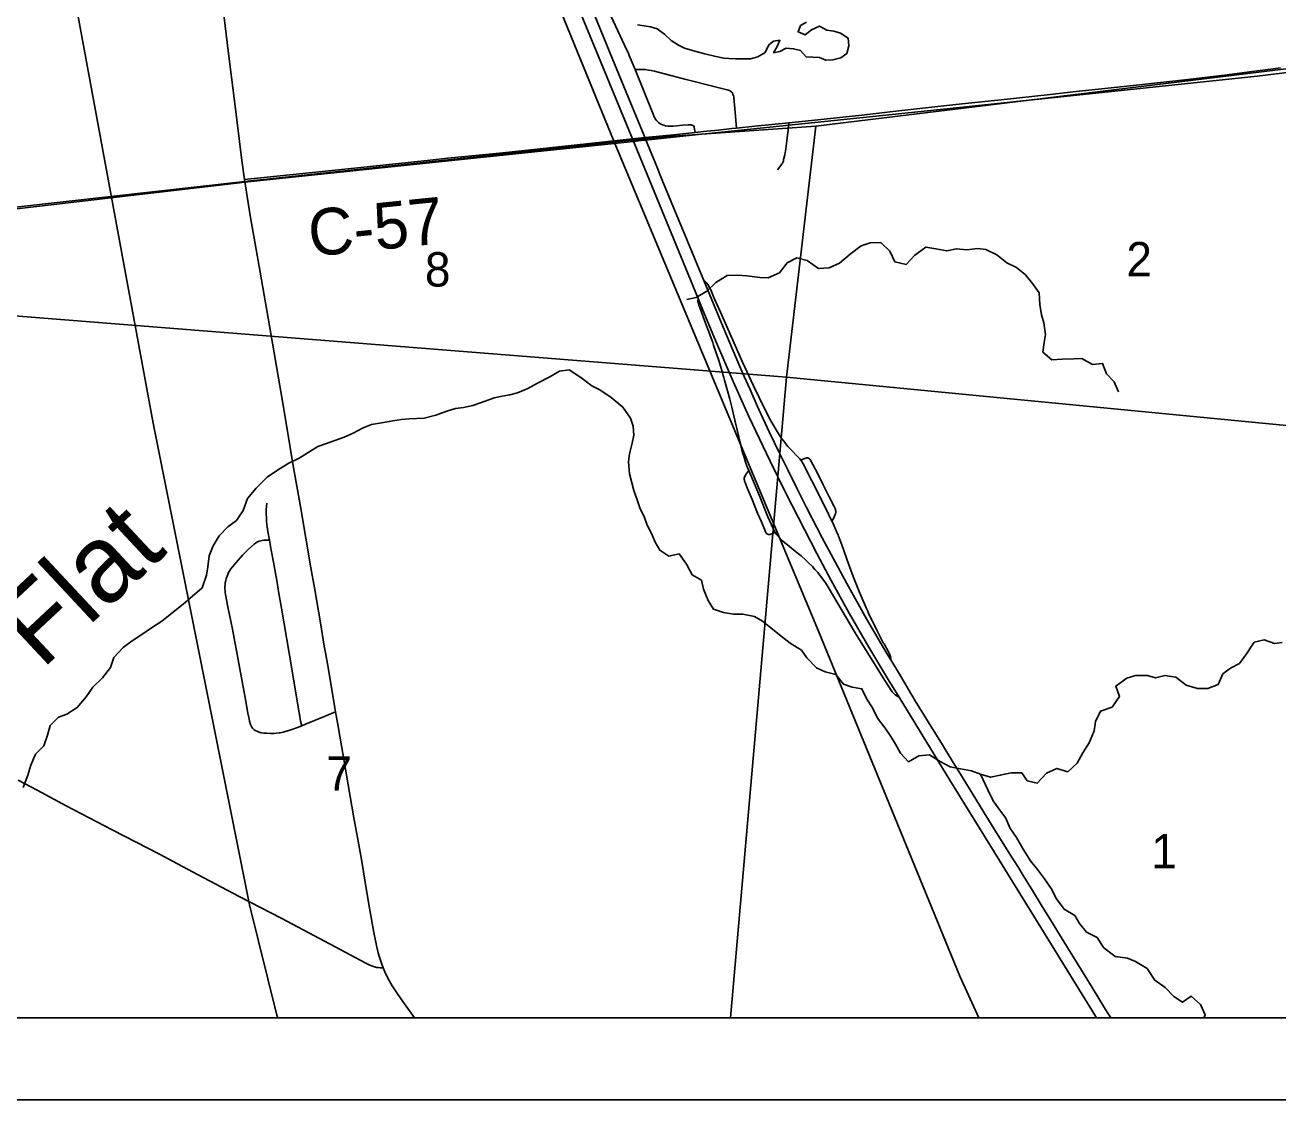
# Model space of a CAD drawing. Extents: x 0 to 34, y -5.4 to 22.
# Drawn here: x 6.179 to 7.705, y 14 to 15.309 of the extents above; entities that cross this region are included whole.
import ezdxf

# ---------------------------------------------------------------- set-up
doc = ezdxf.new("R2010")
doc.units = 0
for name, color, linetype in [('Default', 7, 'Continuous'), ('GM_X_County_Road', 7, 'Continuous'), ('GM_X_County_Road_Text', 7, 'Continuous'), ('GM_X_Interchange_Ramps', 7, 'Continuous'), ('GM_X_Minor_Lake', 7, 'Continuous'), ('GM_X_Minor_River', 7, 'Continuous'), ('GM_X_Minor_River_Text', 7, 'Continuous'), ('GM_X_Rail_Line', 7, 'Continuous'), ('GM_X_Section', 7, 'Continuous'), ('GM_X_Section_Text', 7, 'Continuous'), ('GM_X_Township_Road', 7, 'Continuous'), ('GM_X_US_Route', 7, 'Continuous'), ('SH_Data', 7, 'Continuous')]:
    doc.layers.add(name, color=color, linetype=linetype)

msp = doc.modelspace()

# ---------------------------------------------------------------- linework, layer by layer
at = {"layer": 'Default'}
for points in [[(6.0193, 14.1), (7.0382, 14.1), (7.1062, 14.8804), (6.1044, 14.9597)], [(7.0382, 14.1), (8.0569, 14.1), (8.0946, 14.5055), (8.0215, 14.7918), (7.1062, 14.8804)]]:
    msp.add_lwpolyline(points, close=True, dxfattribs=at)
at = {"layer": 'GM_X_County_Road'}
for points in [[(6.4464, 15.1211), (6.4431, 15.144), (6.4342, 15.2168), (6.4265, 15.2778), (6.4217, 15.3185), (6.4147, 15.3765), (6.4102, 15.4135), (6.4073, 15.4374), (6.4056, 15.4505), (6.4013, 15.4867), (6.3872, 15.6026), (6.3811, 15.6513), (6.3588, 15.8364), (6.3525, 15.8882), (6.3478, 15.927), (6.3428, 15.9686)], [(7.0093, 15.1798), (7.023, 15.1812), (7.0399, 15.183), (7.0453, 15.1835), (7.0677, 15.1859), (7.1092, 15.19), (7.1369, 15.1928), (7.1979, 15.1994), (7.2394, 15.2042), (7.3125, 15.2122), (7.3397, 15.2152), (7.3676, 15.2181), (7.4273, 15.2246), (7.4554, 15.2277), (7.5362, 15.2365), (7.5949, 15.2429), (7.643, 15.2487), (7.6702, 15.252), (7.6831, 15.2536), (7.6989, 15.2557), (7.7077, 15.2571)], [(6.4464, 15.1211), (6.5408, 15.1307), (6.5686, 15.1336), (6.6267, 15.1398), (6.6724, 15.1446), (6.694, 15.1468), (6.7607, 15.1537), (6.8292, 15.161), (6.9036, 15.169), (6.9188, 15.1706)], [(6.9188, 15.1706), (6.9338, 15.172), (6.9431, 15.1729), (6.9688, 15.1755), (6.9953, 15.1783), (7.0054, 15.1794), (7.0093, 15.1798)], [(6.6534, 14.1), (6.6411, 14.1172), (6.6335, 14.1279), (6.6262, 14.1388), (6.6212, 14.1475), (6.6172, 14.1559), (6.6152, 14.161), (6.6134, 14.1652), (6.6127, 14.1676), (6.6111, 14.1726), (6.6104, 14.1752), (6.6092, 14.1793), (6.6074, 14.1862), (6.6038, 14.2039), (6.5975, 14.2404), (6.5932, 14.2652), (6.5887, 14.2928), (6.5847, 14.3151), (6.5796, 14.3435), (6.5726, 14.3839), (6.5661, 14.4219), (6.5604, 14.455), (6.5585, 14.4662), (6.5573, 14.4727), (6.5565, 14.4774), (6.554, 14.4924), (6.5473, 14.531), (6.5453, 14.5426), (6.5435, 14.5526), (6.5387, 14.5812), (6.5314, 14.6236), (6.5272, 14.6481), (6.5149, 14.7202), (6.5053, 14.7747), (6.4983, 14.817), (6.4912, 14.858), (6.4784, 14.9334), (6.4652, 15.008), (6.4533, 15.0773), (6.4464, 15.1211)], [(6.1707, 14.3893), (6.194, 14.3771), (6.229, 14.3581), (6.2852, 14.329), (6.3426, 14.2993), (6.3646, 14.2877), (6.39, 14.2743), (6.4398, 14.2479), (6.4916, 14.2209), (6.5507, 14.1896), (6.5939, 14.1666), (6.5988, 14.1641), (6.6021, 14.1627), (6.6047, 14.162), (6.6071, 14.1614), (6.6095, 14.1611), (6.6116, 14.161), (6.6152, 14.161)]]:
    msp.add_lwpolyline(points, dxfattribs=at)
at = {"layer": 'GM_X_Interchange_Ramps'}
for points in [[(7.2333, 14.536), (7.2333, 14.538), (7.2329, 14.5403), (7.2323, 14.542), (7.2311, 14.5448), (7.2251, 14.5553), (7.2242, 14.5567), (7.2234, 14.5583), (7.2166, 14.5715), (7.2063, 14.5929), (7.2048, 14.5961), (7.2035, 14.5992), (7.1973, 14.6134), (7.1963, 14.6155), (7.1956, 14.6173), (7.189, 14.6335), (7.1882, 14.6356), (7.1874, 14.6376), (7.1818, 14.6531), (7.1739, 14.676), (7.1698, 14.6865), (7.1692, 14.6882), (7.1682, 14.6904), (7.1639, 14.7001), (7.1626, 14.703), (7.1617, 14.7049), (7.1533, 14.7219), (7.137, 14.754), (7.1267, 14.7746), (7.1254, 14.7767), (7.124, 14.7788), (7.1237, 14.7792), (7.1224, 14.7809), (7.1208, 14.7826), (7.1109, 14.7928), (7.1079, 14.796), (7.1056, 14.7989), (7.1029, 14.8024), (7.1007, 14.8053), (7.0974, 14.8102), (7.0948, 14.8141), (7.0885, 14.8249), (7.0876, 14.8264), (7.0868, 14.8281), (7.0798, 14.8413), (7.066, 14.8698), (7.0526, 14.8985), (7.0259, 14.9595), (7.018, 14.9773), (7.014, 14.9866), (7.0123, 14.99), (7.0108, 14.9928), (7.0094, 14.9947), (7.0076, 14.9965), (7.0056, 14.9979)], [(6.9986, 14.9762), (6.9985, 14.973), (6.999, 14.97), (6.9997, 14.9677), (7.0007, 14.965), (7.0066, 14.9493), (7.0153, 14.9257), (7.0165, 14.9224), (7.0176, 14.9191), (7.0242, 14.8994), (7.0259, 14.8937), (7.0279, 14.887), (7.029, 14.8834), (7.0301, 14.8798), (7.0309, 14.8767), (7.0317, 14.8738), (7.0372, 14.8533), (7.0385, 14.8486), (7.0397, 14.8439), (7.0439, 14.8263), (7.0506, 14.7975), (7.0512, 14.7947), (7.052, 14.7913), (7.0532, 14.7873), (7.0542, 14.784), (7.057, 14.7756), (7.0578, 14.7735), (7.0586, 14.7712), (7.0604, 14.7667), (7.0617, 14.7637), (7.0736, 14.7356), (7.0837, 14.7103), (7.09, 14.696), (7.0913, 14.6933), (7.0927, 14.6912), (7.093, 14.6906), (7.0945, 14.6884), (7.0964, 14.6862), (7.0986, 14.6838), (7.1012, 14.6814), (7.1044, 14.6786), (7.1074, 14.6761), (7.1195, 14.6664), (7.124, 14.6626), (7.1298, 14.6575), (7.1339, 14.6535), (7.1378, 14.6497), (7.141, 14.6462), (7.1445, 14.6423), (7.1491, 14.6364), (7.1541, 14.6293), (7.1625, 14.6155), (7.1898, 14.5689), (7.2259, 14.5108), (7.2352, 14.4971), (7.2366, 14.4953), (7.2387, 14.4932), (7.2411, 14.4917), (7.2435, 14.4906)], [(7.1617, 14.7049), (7.163, 14.7074), (7.1644, 14.7102), (7.1652, 14.7122), (7.1658, 14.714), (7.1663, 14.7157), (7.1664, 14.7171), (7.1662, 14.718), (7.166, 14.7189), (7.1656, 14.7203), (7.1641, 14.7235), (7.1584, 14.7347), (7.1511, 14.7493), (7.1445, 14.7624), (7.1383, 14.7739), (7.135, 14.78), (7.1343, 14.7809), (7.1333, 14.7816), (7.1324, 14.7819), (7.1317, 14.782), (7.1307, 14.7819), (7.1299, 14.7817), (7.1261, 14.7802), (7.1237, 14.7792)], [(7.0604, 14.7667), (7.0593, 14.7651), (7.0577, 14.7628), (7.0564, 14.7609), (7.0556, 14.7595), (7.0552, 14.7583), (7.0549, 14.7571), (7.0549, 14.7559), (7.055, 14.7549), (7.0553, 14.7538), (7.056, 14.7518), (7.0586, 14.7453), (7.0645, 14.7312), (7.0712, 14.7145), (7.0757, 14.7039), (7.081, 14.6911), (7.0815, 14.6902), (7.0824, 14.6895), (7.083, 14.689), (7.0843, 14.6887), (7.0855, 14.6887), (7.0863, 14.6888), (7.0871, 14.689), (7.0892, 14.6898), (7.0914, 14.6907), (7.0927, 14.6912)]]:
    msp.add_lwpolyline(points, dxfattribs=at)
at = {"layer": 'GM_X_Minor_Lake'}
msp.add_lwpolyline([(6.9247, 15.3094), (6.9331, 15.3081), (6.9406, 15.3068), (6.9489, 15.3044), (6.9583, 15.2975), (6.9658, 15.2905), (6.9748, 15.2847), (6.9823, 15.2808), (6.9974, 15.2767), (7.0068, 15.2739), (7.0204, 15.2707), (7.0302, 15.269), (7.0363, 15.2685), (7.0442, 15.268), (7.0533, 15.2679), (7.0624, 15.2681), (7.0716, 15.2703), (7.0804, 15.2758), (7.0847, 15.2849), (7.0904, 15.2897), (7.0984, 15.2907), (7.0949, 15.2832), (7.0906, 15.2753), (7.0982, 15.2771), (7.1058, 15.2811), (7.1149, 15.2802), (7.1232, 15.2782), (7.1303, 15.2705), (7.1386, 15.27), (7.1466, 15.2698), (7.1541, 15.2663), (7.1628, 15.2666), (7.1723, 15.2691), (7.18, 15.2746), (7.1824, 15.2837), (7.1814, 15.2932), (7.172, 15.2991), (7.1641, 15.3015), (7.1554, 15.3027), (7.1464, 15.3078), (7.1369, 15.3034), (7.1292, 15.2974), (7.1205, 15.301), (7.1233, 15.3085), (7.1305, 15.3128)], dxfattribs=at)
at = {"layer": 'GM_X_Minor_River'}
for points in [[(6.9848, 14.975), (6.9965, 14.9771), (7.0092, 14.9849), (7.0203, 14.9957), (7.0341, 15.0041), (7.0462, 15.0047), (7.0579, 15.0037), (7.0738, 15.0016), (7.084, 15.0014), (7.0977, 15.0072), (7.107, 15.0196), (7.1188, 15.0255), (7.1316, 15.0222), (7.1451, 15.0125), (7.1584, 15.0134), (7.171, 15.0193), (7.184, 15.03), (7.1974, 15.0401), (7.2081, 15.0437), (7.2213, 15.0442), (7.2321, 15.0338), (7.2383, 15.0208), (7.2519, 15.0175), (7.2627, 15.0287), (7.2761, 15.0387), (7.2882, 15.0366), (7.3014, 15.0341), (7.3132, 15.0366), (7.326, 15.0352), (7.3389, 15.0369), (7.3491, 15.0359), (7.3626, 15.0293), (7.3746, 15.0196), (7.3866, 15.0137), (7.3974, 15.0048), (7.4059, 14.9944), (7.4141, 14.9829), (7.415, 14.9688), (7.417, 14.9563), (7.4199, 14.9464), (7.4219, 14.9323), (7.4202, 14.9225), (7.4185, 14.9107), (7.4293, 14.9014), (7.4422, 14.902), (7.4566, 14.9025), (7.4661, 14.9031), (7.4788, 14.8957), (7.4913, 14.897), (7.496, 14.8844), (7.5053, 14.8747), (7.5108, 14.8625)], [(6.513, 14.7816), (6.5226, 14.7879), (6.5356, 14.796), (6.5451, 14.7989), (6.5565, 14.8033), (6.5676, 14.8073), (6.5786, 14.812), (6.5909, 14.8186), (6.6011, 14.8226), (6.6133, 14.8247), (6.627, 14.8271), (6.6376, 14.8288), (6.647, 14.8294), (6.6652, 14.8303), (6.6793, 14.8338), (6.6938, 14.8393), (6.7033, 14.8421), (6.7128, 14.8435), (6.7245, 14.8456), (6.7394, 14.851), (6.7504, 14.855), (6.7599, 14.8571), (6.7694, 14.8588), (6.7789, 14.8613), (6.7915, 14.8664), (6.8033, 14.8731), (6.8182, 14.8808), (6.8297, 14.8874), (6.8418, 14.8891), (6.8557, 14.8797), (6.8691, 14.8697), (6.8789, 14.8649), (6.8927, 14.8556), (6.9069, 14.8436), (6.9165, 14.8305), (6.9197, 14.8206), (6.9203, 14.8096), (6.9183, 14.7998), (6.915, 14.787), (6.9141, 14.7771), (6.915, 14.7627), (6.9175, 14.7532), (6.9203, 14.7421), (6.925, 14.7295), (6.9283, 14.72), (6.933, 14.7104), (6.9366, 14.7001), (6.9421, 14.6898), (6.9465, 14.6795), (6.952, 14.6695), (6.9629, 14.6621), (6.9758, 14.6649), (6.9847, 14.6527), (6.9913, 14.6396), (7.0029, 14.633), (7.0053, 14.622), (7.0108, 14.6082), (7.0174, 14.5979), (7.0295, 14.5935), (7.0419, 14.5918), (7.0533, 14.5916), (7.0672, 14.5887), (7.0773, 14.5832), (7.0874, 14.575), (7.0997, 14.565), (7.1109, 14.5561), (7.1244, 14.5479), (7.1311, 14.5383), (7.143, 14.5263), (7.1535, 14.5212), (7.1663, 14.5183), (7.1756, 14.5064), (7.1861, 14.5028), (7.1982, 14.5007), (7.204, 14.4881), (7.211, 14.4774), (7.2173, 14.4651), (7.2265, 14.4528), (7.2335, 14.4428), (7.2391, 14.4333), (7.2453, 14.4222), (7.255, 14.4118), (7.2676, 14.4191), (7.2805, 14.4204), (7.2936, 14.4122), (7.3056, 14.4056), (7.3184, 14.4031), (7.3316, 14.401), (7.3425, 14.3966), (7.3549, 14.393), (7.3667, 14.3954), (7.38, 14.3982), (7.3929, 14.3984), (7.3995, 14.3888), (7.4116, 14.3856), (7.4228, 14.3979), (7.4357, 14.4037), (7.4489, 14.3997), (7.4601, 14.4101), (7.4671, 14.4229), (7.4749, 14.4349)], [(6.1767, 14.3803), (6.1823, 14.3954), (6.1863, 14.4078), (6.1918, 14.421), (6.2018, 14.4311), (6.2065, 14.4443), (6.2098, 14.456), (6.2198, 14.4661), (6.23, 14.4697), (6.2427, 14.4778), (6.2535, 14.4909), (6.2616, 14.5029), (6.2732, 14.5141), (6.2832, 14.5265), (6.2872, 14.5389), (6.2984, 14.5512), (6.3095, 14.559), (6.3202, 14.566), (6.3344, 14.5757), (6.3455, 14.5831), (6.3577, 14.5927), (6.3716, 14.6039), (6.3831, 14.6135), (6.3946, 14.6236), (6.4002, 14.639), (6.4015, 14.6493), (6.4032, 14.6625), (6.4083, 14.6749), (6.4153, 14.6869), (6.4261, 14.6981), (6.4365, 14.7056), (6.4446, 14.7179), (6.4498, 14.7323), (6.4606, 14.745), (6.4741, 14.7584), (6.4878, 14.768), (6.5005, 14.7754), (6.513, 14.7816)], [(7.4749, 14.4349), (7.4808, 14.4496), (7.4825, 14.461), (7.4887, 14.4734), (7.5028, 14.4784), (7.5118, 14.4912), (7.5074, 14.5041), (7.5208, 14.5138), (7.5315, 14.517), (7.5459, 14.5171), (7.5557, 14.5139), (7.5671, 14.5168), (7.5803, 14.515), (7.593, 14.505), (7.6069, 14.5009), (7.6194, 14.5011), (7.632, 14.5058), (7.6375, 14.519), (7.6471, 14.5257), (7.6578, 14.5315), (7.6667, 14.5435), (7.676, 14.5574), (7.6881, 14.5602), (7.7005, 14.5558), (7.71, 14.5572)], [(7.3426, 14.3966), (7.3517, 14.3775), (7.3582, 14.3641), (7.366, 14.353), (7.3734, 14.343), (7.3781, 14.3315), (7.3863, 14.3196), (7.3947, 14.3054), (7.4036, 14.2913), (7.4121, 14.2805), (7.4206, 14.2694), (7.4287, 14.2575), (7.4353, 14.2448), (7.4446, 14.2322), (7.4573, 14.2247), (7.4632, 14.2148), (7.4717, 14.2044), (7.4845, 14.1977), (7.4922, 14.1855), (7.5064, 14.1746), (7.5215, 14.1728), (7.5313, 14.1685), (7.5455, 14.1599), (7.5548, 14.1457), (7.5675, 14.1371), (7.5779, 14.126), (7.5887, 14.1189), (7.5991, 14.1264), (7.6103, 14.1163), (7.6161, 14.1037), (7.6147, 14.1)]]:
    msp.add_lwpolyline(points, dxfattribs=at)
at = {"layer": 'GM_X_Rail_Line'}
for points in [[(4.0439, 14.8538), (4.7395, 14.9295), (4.8765, 14.9444), (6.1164, 15.0793), (6.4403, 15.1171), (6.4463, 15.1177), (6.92, 15.1674), (6.9294, 15.1684), (6.9348, 15.169), (6.9914, 15.1749), (7.0389, 15.1799), (7.3134, 15.2082), (7.6796, 15.247), (7.6929, 15.2483), (7.8942, 15.2734), (7.8983, 15.2739), (8.1702, 15.3079), (8.1991, 15.5295), (8.9, 15.5944), (8.9, 19.2127)], [(6.1298, 17.0307), (6.0905, 16.9105), (6.0657, 16.8233), (6.0521, 16.7659), (6.0427, 16.7106), (6.0374, 16.6619), (6.0337, 16.61), (6.035, 16.5368), (6.0346, 16.4766), (6.0418, 16.428), (6.0526, 16.3516), (6.0987, 16.1024), (6.1764, 15.688), (6.2405, 15.3368), (6.3349, 14.8243), (6.4523, 14.2374), (6.4858, 14.1034), (6.4871, 14.1)], [(6.1298, 17.0307), (6.1657, 16.9396), (6.2331, 16.7878), (6.3387, 16.522), (6.5579, 15.9912), (6.6517, 15.7661), (6.8965, 15.1669), (7.1452, 14.5708), (7.2659, 14.2765), (7.3176, 14.1508), (7.3404, 14.1)]]:
    msp.add_lwpolyline(points, dxfattribs=at)
msp.add_lwpolyline([(2.9527, 14.1), (8.0559, 14.1), (8.0925, 14.4946), (8.0933, 14.5029), (8.1066, 14.6429), (8.1702, 15.3079), (7.8983, 15.2739), (7.8942, 15.2734), (7.6929, 15.2483), (7.6796, 15.247), (7.3134, 15.2082), (7.0389, 15.1799), (6.9914, 15.1749), (6.9348, 15.169), (6.9294, 15.1684), (6.92, 15.1674), (6.4463, 15.1177), (6.4403, 15.1171), (6.1164, 15.0793), (4.8765, 14.9444), (4.7395, 14.9295), (4.0439, 14.8538), (3.0059, 14.7462), (2.9641, 14.2324)], close=True, dxfattribs=at)
at = {"layer": 'GM_X_Section'}
for points in [[(7.7181, 15.2564), (7.8967, 15.2761), (8.0215, 14.7918), (7.1062, 14.8804), (7.1421, 15.1859)], [(7.1421, 15.1859), (7.1062, 14.8804), (6.1044, 14.9597), (6.1164, 15.0815), (6.4432, 15.1181), (6.9566, 15.1729)]]:
    msp.add_lwpolyline(points, close=True, dxfattribs=at)
at = {"layer": 'GM_X_Township_Road'}
for points in [[(6.9953, 15.1783), (6.9945, 15.1824), (6.9938, 15.185), (6.9931, 15.1862), (6.9924, 15.1867), (6.9911, 15.1872), (6.9901, 15.1875), (6.9887, 15.1877), (6.9867, 15.1876), (6.98, 15.1873), (6.9682, 15.1861), (6.9658, 15.1859), (6.9636, 15.1858), (6.9614, 15.1861), (6.9589, 15.1865), (6.9569, 15.187), (6.9552, 15.1876), (6.9533, 15.1886), (6.952, 15.1894), (6.9504, 15.1905), (6.9491, 15.1917), (6.9481, 15.1929), (6.9468, 15.1947), (6.9453, 15.1974), (6.9439, 15.2006), (6.922, 15.2548), (6.9149, 15.2719), (6.9138, 15.2748), (6.912, 15.2785), (6.8979, 15.3082), (6.8892, 15.3271)], [(6.922, 15.2548), (6.928, 15.255), (6.9314, 15.2551), (6.9345, 15.2548), (6.9383, 15.2541), (6.9414, 15.2536), (6.9456, 15.2528), (6.9579, 15.2498), (6.9826, 15.2434), (7.0242, 15.2326), (7.0339, 15.2302), (7.0369, 15.2293), (7.0382, 15.2285), (7.0394, 15.2276), (7.04, 15.2269), (7.0405, 15.2261), (7.0411, 15.2247), (7.0417, 15.2233), (7.0421, 15.2219), (7.0424, 15.2204), (7.044, 15.2032), (7.045, 15.1879), (7.0453, 15.1835)], [(7.0952, 15.1329), (7.0995, 15.1382), (7.1007, 15.1399), (7.1013, 15.141), (7.1021, 15.1425), (7.1025, 15.1438), (7.1028, 15.1453), (7.1031, 15.1466), (7.1041, 15.1511), (7.1054, 15.1584), (7.1068, 15.1683), (7.1077, 15.175), (7.1083, 15.1807), (7.1088, 15.1853), (7.1092, 15.19)], [(6.5161, 14.4557), (6.5147, 14.4613), (6.5142, 14.4636), (6.5135, 14.4668), (6.5128, 14.4713), (6.5081, 14.5004), (6.5039, 14.5251), (6.4914, 14.5988), (6.4879, 14.6192), (6.486, 14.6303), (6.4816, 14.6551), (6.4789, 14.6695), (6.4766, 14.6818), (6.4748, 14.6921), (6.4741, 14.6978), (6.4733, 14.7045), (6.4729, 14.7099), (6.4728, 14.7129), (6.4728, 14.716), (6.4728, 14.7186), (6.4732, 14.7231), (6.4736, 14.7268)], [(6.5573, 14.4727), (6.5445, 14.4675), (6.5206, 14.4576), (6.5161, 14.4557), (6.5108, 14.4537), (6.5038, 14.451), (6.5003, 14.4499), (6.496, 14.4486), (6.4932, 14.4479), (6.4899, 14.4472), (6.4884, 14.447), (6.4848, 14.4466), (6.482, 14.4463), (6.4779, 14.4463), (6.4734, 14.4466), (6.4698, 14.4467), (6.4665, 14.4472), (6.4642, 14.448), (6.4614, 14.449), (6.4594, 14.4499), (6.4581, 14.4509), (6.4573, 14.4516), (6.4561, 14.4528), (6.4553, 14.4541), (6.4544, 14.4557), (6.4538, 14.4572), (6.4533, 14.4586), (6.4526, 14.4612), (6.4519, 14.4642), (6.4505, 14.471), (6.4475, 14.4878), (6.4316, 14.5734), (6.4296, 14.5831), (6.4282, 14.5906), (6.4262, 14.6004), (6.4233, 14.6157), (6.4229, 14.6179), (6.4227, 14.6201), (6.4225, 14.6225), (6.4224, 14.6249), (6.4227, 14.6278), (6.4229, 14.6299), (6.4236, 14.6327), (6.4241, 14.6351), (6.4251, 14.6379), (6.426, 14.64), (6.427, 14.6423), (6.4286, 14.6448), (6.4298, 14.6467), (6.4317, 14.6494), (6.4361, 14.6545), (6.4439, 14.6635), (6.451, 14.6706), (6.458, 14.6769), (6.4603, 14.6784), (6.462, 14.6796), (6.4632, 14.6801), (6.4642, 14.6806), (6.4663, 14.6811), (6.468, 14.6814), (6.4699, 14.6816), (6.4766, 14.6818)]]:
    msp.add_lwpolyline(points, dxfattribs=at)
at = {"layer": 'GM_X_US_Route'}
for points in [[(6.513, 16.1582), (6.5275, 16.1223), (6.5729, 16.0113), (6.5938, 15.9611), (6.6401, 15.8489), (6.6602, 15.7999), (6.6913, 15.724), (6.7164, 15.6624), (6.7363, 15.6145), (6.8369, 15.3693), (6.8669, 15.2965), (6.9119, 15.1873), (6.9188, 15.1706)], [(6.8635, 15.3433), (6.8794, 15.3046), (6.8913, 15.2757), (6.914, 15.2203), (6.9257, 15.1919), (6.9324, 15.1755), (6.9338, 15.172)], [(6.9188, 15.1706), (6.9986, 14.9762), (7.0045, 14.9619), (7.0197, 14.925), (7.0323, 14.8959), (7.0414, 14.8749), (7.0606, 14.8324), (7.0863, 14.7779), (7.1056, 14.7389), (7.1432, 14.6654), (7.1608, 14.6325), (7.1828, 14.5928), (7.2066, 14.5514), (7.2303, 14.512), (7.2435, 14.4906), (7.3054, 14.3896), (7.3592, 14.3023), (7.3788, 14.2706), (7.4364, 14.177), (7.4781, 14.1093), (7.4838, 14.1)], [(6.9338, 15.172), (6.9394, 15.1584), (6.9463, 15.1417), (6.9551, 15.1204), (7.0056, 14.9979), (7.0291, 14.9411), (7.049, 14.8942), (7.0548, 14.8811), (7.0615, 14.866), (7.0707, 14.8453), (7.0853, 14.8137), (7.0983, 14.7869), (7.1078, 14.7673), (7.1194, 14.7441), (7.1306, 14.7217), (7.1498, 14.6847), (7.1799, 14.6289), (7.2039, 14.5861), (7.2287, 14.5437), (7.2333, 14.536), (7.2438, 14.5185), (7.2632, 14.4861), (7.2789, 14.4606), (7.2961, 14.4326), (7.3081, 14.413), (7.3213, 14.3913), (7.3324, 14.3734), (7.3471, 14.3498), (7.361, 14.3274), (7.3783, 14.2995), (7.3879, 14.2841), (7.3946, 14.2732), (7.4045, 14.2572), (7.4166, 14.2376), (7.4279, 14.2194), (7.4446, 14.1921), (7.4656, 14.158), (7.4784, 14.1371), (7.4949, 14.1102), (7.5011, 14.1)]]:
    msp.add_lwpolyline(points, dxfattribs=at)
at = {"layer": 'SH_Data'}
for p, q in [((2.1, 14.1), (8.9, 14.1)), ((2, 14), (9, 14))]:
    msp.add_line(p, q, dxfattribs=at)

# ---------------------------------------------------------------- texts
at = {"layer": 'GM_X_County_Road_Text'}
msp.add_text('C-57', height=0.05682, rotation=5.8467, dxfattribs=at).set_placement((6.5269, 15.0269))
at = {"layer": 'GM_X_Minor_River_Text'}
msp.add_text('Flat', height=0.09471, rotation=43.0301, dxfattribs=at).set_placement((6.1994, 14.5233))
at = {"layer": 'GM_X_Section_Text'}
for s, p in [('2', (7.5202, 15.003)), ('8', (6.666, 14.9906)), ('7', (6.546, 14.3766)), ('1', (7.5506, 14.2819))]:
    msp.add_text(s, height=0.0419, rotation=0, dxfattribs=at).set_placement(p)

doc.saveas('drawing.dxf')
